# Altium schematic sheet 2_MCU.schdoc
size 309 x 223 mm; Symbol: Artery_A4; Device: Artery_A4; Company: Artery Technology; Drawed: SD; Version: 1.1; Page Size: A4; @Project Name: p_AT-START-F437; @Page Count: 5; @Update Date: 2023-04-14 17:11:57; @Create Date: 2022-12-01; @Schematic Name: AT-START-F437 V1.1; @Page No: 2; @Page Name: MCU
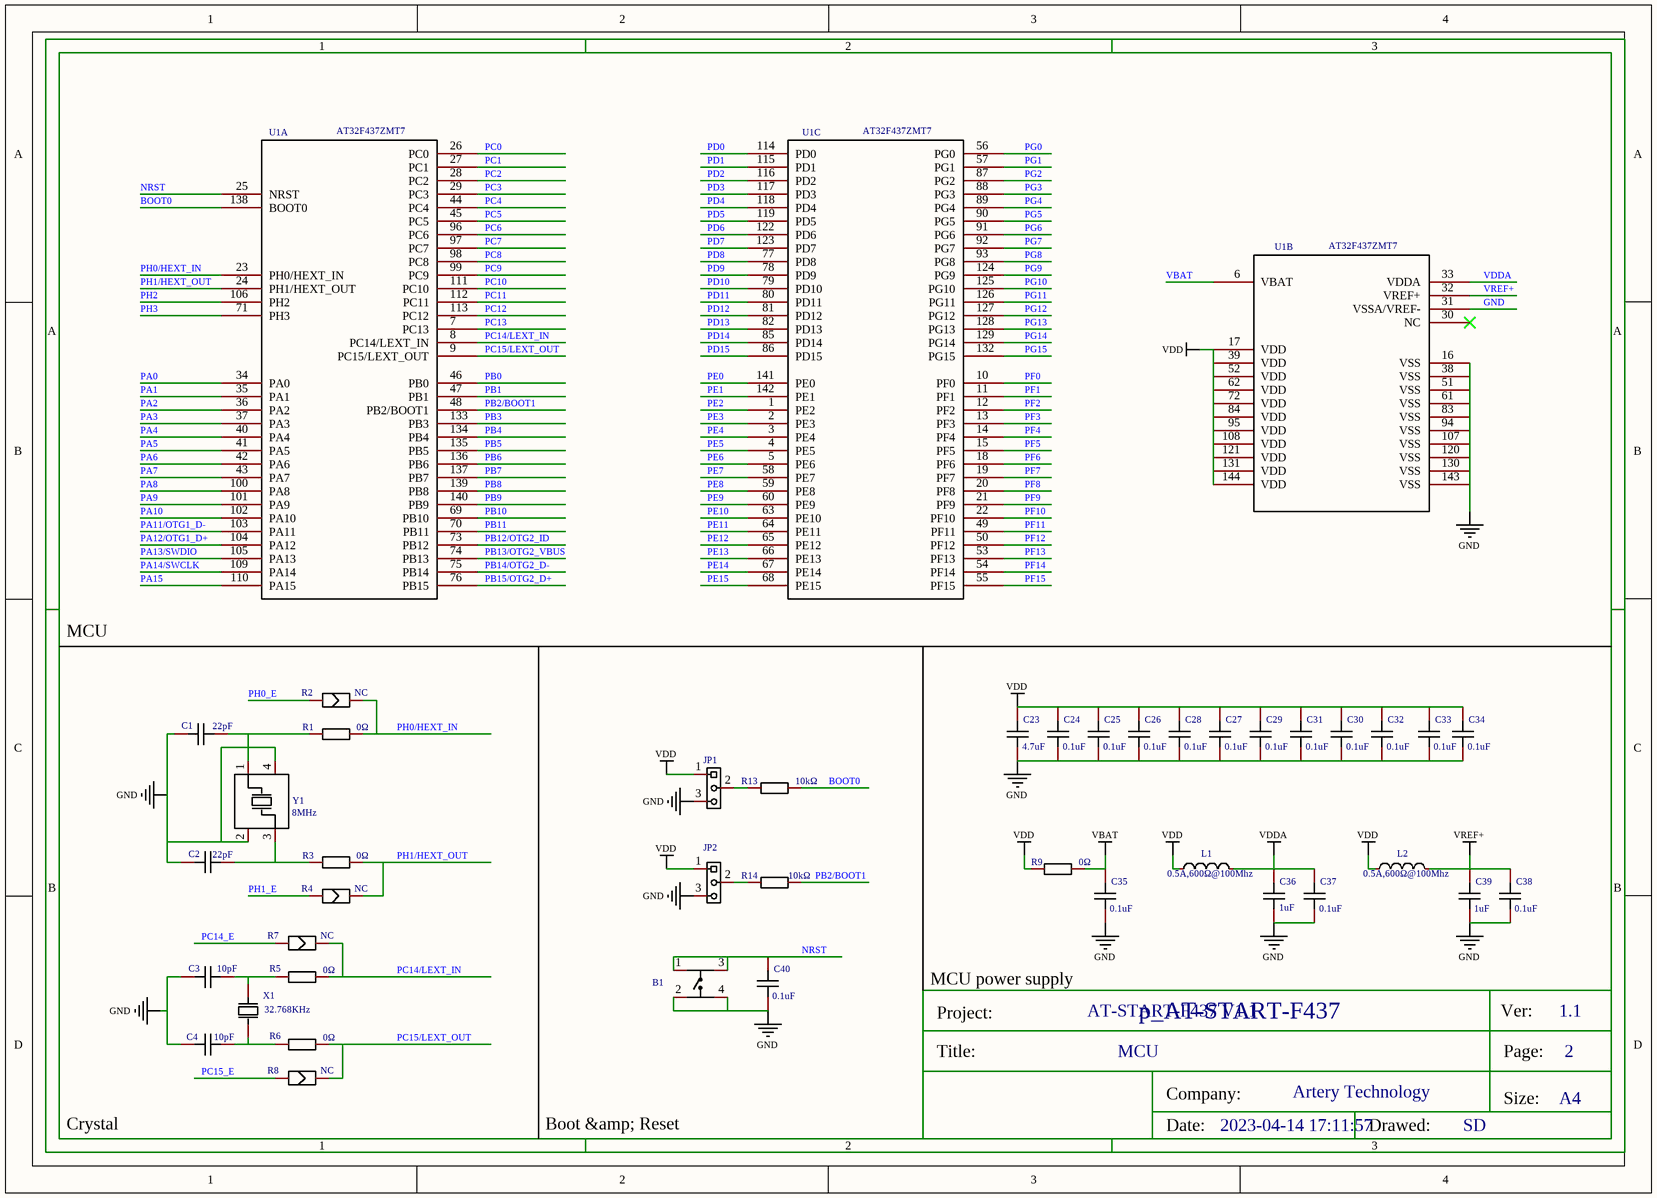
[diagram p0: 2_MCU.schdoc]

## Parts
B1  贴片按键6*6*5 黑色  [SW-SMD_4P-L6.0-W6.0-P4.50-LS9.0]  (value not drawn)
C1  22pF  [0603_C-M]
C2  22pF  [0603_C-M]
C3  10pF  [0603_C-M]
C4  10pF  [0603_C-M]
C23  4.7uF  [0603_C-M]
C24  0.1uF  [0603_C-M]
C25  0.1uF  [0603_C-M]
C26  0.1uF  [0603_C-M]
C27  0.1uF  [0603_C-M]
C28  0.1uF  [0603_C-M]
C29  0.1uF  [0603_C-M]
C30  0.1uF  [0603_C-M]
C31  0.1uF  [0603_C-M]
C32  0.1uF  [0603_C-M]
C33  0.1uF  [0603_C-M]
C34  0.1uF  [0603_C-M]
C35  0.1uF  [0603_C-M]
C36  1uF  [0603_C-M]
C37  0.1uF  [0603_C-M]
C38  0.1uF  [0603_C-M]
C39  1uF  [0603_C-M]
C40  0.1uF  [0603_C-M]
JP1  Jumper 1x3P  [HEADER 1X3]  (value not drawn)
JP2  Jumper 1x3P  [HEADER 1X3]  (value not drawn)
L1  0.5A,600Ω@100Mhz  [0603_L]
L2  0.5A,600Ω@100Mhz  [0603_L]
R1  0Ω  [R0603]
R2  NC  [SB-PAD]
R3  0Ω  [R0603]
R4  NC  [SB-PAD]
R5  0Ω  [R0603]
R6  0Ω  [R0603]
R7  NC  [SB-PAD]
R8  NC  [SB-PAD]
R9  0Ω  [R0603]
R13  10kΩ  [R0603]
R14  10kΩ  [R0603]
U1  AT32F437ZMT7  [LQFP144_20*20]  (parts A,B,C of 3)
X1  32.768KHz  [FC-12M_L2.0-W1.2]
Y1  8MHz  [OSC-SMD_4P-L5.0-W3.2-BL]

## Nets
GND: B1.2 B1.4 C1.1 C2.1 C3.1 C4.1 C23.2 C24.2 C25.2 C26.2 C27.2 C28.2 C29.2 C30.2 C31.2 C32.2 C33.2 C34.2 C35.2 C36.2 C37.2 C38.2 C39.2 C40.2 JP1.3 JP2.3 U1.16(VSS) U1.31(VSSA/VREF-) U1.38(VSS) U1.51(VSS) U1.61(VSS) U1.83(VSS) U1.94(VSS) U1.107(VSS) U1.120(VSS) U1.130(VSS) U1.143(VSS) Y1.2(GND) Y1.4(GND)
VBAT: C35.1 R9.1 U1.6(VBAT)
VDD: C23.1 C24.1 C25.1 C26.1 C27.1 C28.1 C29.1 C30.1 C31.1 C32.1 C33.1 C34.1 JP1.1 JP2.1 L1.1 L2.1 R9.2 U1.17(VDD) U1.39(VDD) U1.52(VDD) U1.62(VDD) U1.72(VDD) U1.84(VDD) U1.95(VDD) U1.108(VDD) U1.121(VDD) U1.131(VDD) U1.144(VDD)
VDDA: C36.1 C37.1 L1.2 U1.33(VDDA)
VREF+: C38.1 C39.1 L2.2 U1.32(VREF+)
BOOT0: R13.2 U1.138(BOOT0)
NRST: B1.1 B1.3 C40.1 U1.25(NRST)
PA0: U1.34(PA0)
PA1: U1.35(PA1)
PA2: U1.36(PA2)
PA3: U1.37(PA3)
PA4: U1.40(PA4)
PA5: U1.41(PA5)
PA6: U1.42(PA6)
PA7: U1.43(PA7)
PA8: U1.100(PA8)
PA9: U1.101(PA9)
PA10: U1.102(PA10)
PA11/OTG1_D-: U1.103(PA11)
PA12/OTG1_D+: U1.104(PA12)
PA13/SWDIO: U1.105(PA13)
PA14/SWCLK: U1.109(PA14)
PA15: U1.110(PA15)
PB0: U1.46(PB0)
PB1: U1.47(PB1)
PB2/BOOT1: R14.2 U1.48(PB2/BOOT1)
PB3: U1.133(PB3)
PB4: U1.134(PB4)
PB5: U1.135(PB5)
PB6: U1.136(PB6)
PB7: U1.137(PB7)
PB8: U1.139(PB8)
PB9: U1.140(PB9)
PB10: U1.69(PB10)
PB11: U1.70(PB11)
PB12/OTG2_ID: U1.73(PB12)
PB13/OTG2_VBUS: U1.74(PB13)
PB14/OTG2_D-: U1.75(PB14)
PB15/OTG2_D+: U1.76(PB15)
PC0: U1.26(PC0)
PC1: U1.27(PC1)
PC2: U1.28(PC2)
PC3: U1.29(PC3)
PC4: U1.44(PC4)
PC5: U1.45(PC5)
PC6: U1.96(PC6)
PC7: U1.97(PC7)
PC8: U1.98(PC8)
PC9: U1.99(PC9)
PC10: U1.111(PC10)
PC11: U1.112(PC11)
PC12: U1.113(PC12)
PC13: U1.7(PC13)
PC14/LEXT_IN: R5.2 R7.2 U1.8(PC14/LEXT_IN)
PC14_E: R7.1
PC15/LEXT_OUT: R6.2 R8.2 U1.9(PC15/LEXT_OUT)
PC15_E: R8.1
PD0: U1.114(PD0)
PD1: U1.115(PD1)
PD2: U1.116(PD2)
PD3: U1.117(PD3)
PD4: U1.118(PD4)
PD5: U1.119(PD5)
PD6: U1.122(PD6)
PD7: U1.123(PD7)
PD8: U1.77(PD8)
PD9: U1.78(PD9)
PD10: U1.79(PD10)
PD11: U1.80(PD11)
PD12: U1.81(PD12)
PD13: U1.82(PD13)
PD14: U1.85(PD14)
PD15: U1.86(PD15)
PE0: U1.141(PE0)
PE1: U1.142(PE1)
PE2: U1.1(PE2)
PE3: U1.2(PE3)
PE4: U1.3(PE4)
PE5: U1.4(PE5)
PE6: U1.5(PE6)
PE7: U1.58(PE7)
PE8: U1.59(PE8)
PE9: U1.60(PE9)
PE10: U1.63(PE10)
PE11: U1.64(PE11)
PE12: U1.65(PE12)
PE13: U1.66(PE13)
PE14: U1.67(PE14)
PE15: U1.68(PE15)
PF0: U1.10(PF0)
PF1: U1.11(PF1)
PF2: U1.12(PF2)
PF3: U1.13(PF3)
PF4: U1.14(PF4)
PF5: U1.15(PF5)
PF6: U1.18(PF6)
PF7: U1.19(PF7)
PF8: U1.20(PF8)
PF9: U1.21(PF9)
PF10: U1.22(PF10)
PF11: U1.49(PF11)
PF12: U1.50(PF12)
PF13: U1.53(PF13)
PF14: U1.54(PF14)
PF15: U1.55(PF15)
PG0: U1.56(PG0)
PG1: U1.57(PG1)
PG2: U1.87(PG2)
PG3: U1.88(PG3)
PG4: U1.89(PG4)
PG5: U1.90(PG5)
PG6: U1.91(PG6)
PG7: U1.92(PG7)
PG8: U1.93(PG8)
PG9: U1.124(PG9)
PG10: U1.125(PG10)
PG11: U1.126(PG11)
PG12: U1.127(PG12)
PG13: U1.128(PG13)
PG14: U1.129(PG14)
PG15: U1.132(PG15)
PH0/HEXT_IN: R1.2 R2.2 U1.23(PH0/HEXT_IN)
PH0_E: R2.1
PH1/HEXT_OUT: R3.2 R4.2 U1.24(PH1/HEXT_OUT)
PH1_E: R4.1
PH2: U1.106(PH2)
PH3: U1.71(PH3)
NetC1_2: C1.2 R1.1 Y1.1(OSC1)
NetC2_2: C2.2 R3.1 Y1.3(OSC2)
NetC3_2: C3.2 R5.1 X1.2(OSC2)
NetC4_2: C4.2 R6.1 X1.1(OSC1)
NetJP1_2: JP1.2 R13.1
NetJP2_2: JP2.2 R14.1

Not connected (* = marked no-connect by the designer): U1 30(NC)*

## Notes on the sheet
- MCU
- MCU power supply
- Crystal
- Boot &amp; Reset

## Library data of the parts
B1 = K2-1102SP-C3SC-04: Manufacturer: Korean Hroparts Elec; Paste Type: expand; Convert to PCB: yes
C1 C2 = 22pF: Convert to PCB: yes
C3 C4 = 10pF: Convert to PCB: yes
C23 = 4.7uF: Convert to PCB: yes
C24-C35 C37 C38 C40 = 0.1uF: Convert to PCB: yes
C36 C39 = 1uF: Convert to PCB: yes
JP1 JP2 = Jumper 1x3P: Convert to PCB: yes
L1 L2 = 0.5A,600Ω@100Mhz: Convert to PCB: yes
R1 R3 R5 R6 R9 = 0603WAF0000T5E: 电阻类型:厚膜电阻;阻值:0Ω;精度:±1%;功率:100mW;最大工作电压:75V;工作温度范围:-55℃~+155℃;; Manufacturer: UNI-ROYAL(厚声); Add into BOM: yes; Tolerance: ±1%; Power(Watts): 100mW; Overload Voltage (Max): 75V
R2 R4 R7 R8 = NC: Convert to PCB: yes
R13 R14 = 0603WAF1002T5E: 电阻类型:厚膜电阻;阻值:10kΩ;精度:±1%;功率:100mW;温度系数:±100ppm/℃;最大工作电压:75V;工作温度范围:-55℃~+155℃;; Manufacturer: UNI-ROYAL(厚声); Add into BOM: yes; Tolerance: ±1%; Power(Watts): 100mW; Overload Voltage (Max): 75V
U1 = AT32F437ZMT7: Convert to PCB: yes
X1 = FC-12M32.768KHZ7PF20PPM: Manufacturer: EPSON; Paste Type: expand; Convert to PCB: yes
Y1 = SMD-5032_4P8M20pf20ppm: Manufacturer: TAE; Paste Type: recommend; Convert to PCB: yes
